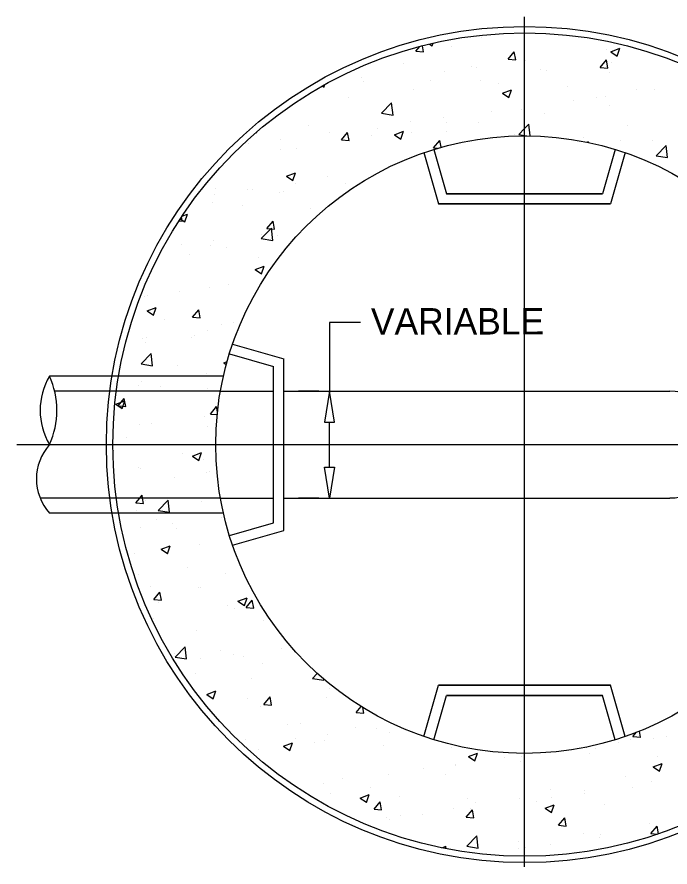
# Model space of a CAD drawing. Extents: x 6712067 to 6713867, y 1867712 to 1869162.
# Drawn here: x 6713210.3 to 6713358.3, y 1867926.4 to 1868119 of the extents above; entities that cross this region are included whole.
import ezdxf

# ---------------------------------------------------------------- set-up
doc = ezdxf.new("R2010")
doc.units = 0
for name, color, linetype in [('G-MARK', 7, 'Continuous'), ('G-TEXT', 7, 'Continuous'), ('Misc CnstDet(22)', 7, 'Continuous')]:
    doc.layers.add(name, color=color, linetype=linetype)

msp = doc.modelspace()

# ---------------------------------------------------------------- linework, layer by layer
at = {"layer": 'G-MARK'}
for p, q in [((6713288.14, 1868049.81), (6713281.14, 1868049.81)), ((6713281.14, 1868049.81), (6713281.14, 1868034.25)), ((6713281.14, 1868017.05), (6713281.14, 1868027.26))]:
    msp.add_line(p, q, dxfattribs=at)
at = {"layer": 'G-TEXT'}
for points in [[(6713279.98, 1868027.26), (6713282.31, 1868027.26), (6713281.14, 1868034.25)], [(6713279.98, 1868017.05), (6713282.31, 1868017.05), (6713281.14, 1868010.04)]]:
    msp.add_lwpolyline(points, close=True, dxfattribs=at)
at = {"layer": 'Misc CnstDet(22)'}
for p, q in [((6713325.33, 1867926.44), (6713325.33, 1868119.03)), ((6713325.89, 1868115.36), (6713325.89, 1868115.36)), ((6713303.83, 1868112.91), (6713304.41, 1868112.52)), ((6713304.4, 1868112.52), (6713304.6, 1868113.1)), ((6713315.65, 1868114.46), (6713315.65, 1868114.46)), ((6713300.68, 1868111.28), (6713301.58, 1868112.35)), ((6713300.68, 1868111.28), (6713302.43, 1868111.13)), ((6713302.43, 1868111.13), (6713302.18, 1868112.5)), ((6713308.89, 1868112.44), (6713308.89, 1868112.44)), ((6713321.59, 1868109.46), (6713322.99, 1868111.13)), ((6713323.34, 1868109.3), (6713322.99, 1868111.12)), ((6713344.01, 1868111.58), (6713344.01, 1868111.58)), ((6713344.85, 1868111.17), (6713346.89, 1868111.95)), ((6713344.85, 1868111.17), (6713346.3, 1868110.19)), ((6713346.3, 1868110.18), (6713346.89, 1868111.95)), ((6713321.59, 1868109.46), (6713323.34, 1868109.3)), ((6713325.6, 1868109.16), (6713325.6, 1868109.16)), ((6713342.5, 1868107.62), (6713343.9, 1868109.3)), ((6713344.24, 1868107.47), (6713343.9, 1868109.3)), ((6713297.81, 1868108.52), (6713297.81, 1868108.52)), ((6713313.38, 1868107.86), (6713313.38, 1868107.86)), ((6713314.56, 1868107.7), (6713314.56, 1868107.7)), ((6713328.94, 1868107.21), (6713328.94, 1868107.21)), ((6713342.5, 1868107.62), (6713344.24, 1868107.47)), ((6713344.98, 1868108.68), (6713344.98, 1868108.68)), ((6713288.4, 1868105.26), (6713288.4, 1868105.26)), ((6713307.26, 1868106.75), (6713307.26, 1868106.75)), ((6713330.26, 1868106.81), (6713330.26, 1868106.81)), ((6713344.5, 1868106.54), (6713344.5, 1868106.54)), ((6713279.51, 1868103.4), (6713279.91, 1868103.12)), ((6713279.91, 1868103.12), (6713280.12, 1868103.74)), ((6713288.85, 1868104.32), (6713288.85, 1868104.32)), ((6713303.97, 1868104.6), (6713303.97, 1868104.6)), ((6713315.29, 1868104.75), (6713315.29, 1868104.75)), ((6713319.53, 1868103.95), (6713319.53, 1868103.95)), ((6713335.09, 1868103.28), (6713335.09, 1868103.28)), ((6713300.16, 1868102.57), (6713300.16, 1868102.57)), ((6713320.35, 1868101.77), (6713322.4, 1868102.55)), ((6713320.35, 1868101.77), (6713321.81, 1868100.78)), ((6713321.81, 1868100.78), (6713322.4, 1868102.55)), ((6713350.65, 1868102.63), (6713350.65, 1868102.63)), ((6713354.67, 1868102.5), (6713354.67, 1868102.5)), ((6713285.43, 1868100.7), (6713285.43, 1868100.7)), ((6713292.94, 1868097.21), (6713295.21, 1868099.58)), ((6713295.53, 1868096.81), (6713295.21, 1868099.58)), ((6713336.34, 1868100.08), (6713336.34, 1868100.08)), ((6713341.68, 1868100.89), (6713341.68, 1868100.89)), ((6713343.64, 1868101.05), (6713343.64, 1868101.05)), ((6713317.93, 1868097.66), (6713317.93, 1868097.66)), ((6713324.68, 1868097.97), (6713324.68, 1868097.97)), ((6713344.63, 1868098.97), (6713344.63, 1868098.97)), ((6713292.94, 1868097.21), (6713295.53, 1868096.81)), ((6713306.89, 1868096.2), (6713306.89, 1868096.2)), ((6713329.9, 1868097.1), (6713329.9, 1868097.1)), ((6713276.46, 1868094.36), (6713276.46, 1868094.36)), ((6713292.02, 1868093.7), (6713292.02, 1868093.7)), ((6713299.59, 1868095.25), (6713299.59, 1868095.25)), ((6713307.68, 1868095.06), (6713307.68, 1868095.06)), ((6713314.94, 1868095.06), (6713314.94, 1868095.06)), ((6713324.05, 1868092.38), (6713325.33, 1868093.73)), ((6713325.33, 1868093.73), (6713326.32, 1868094.76)), ((6713326.63, 1868092.1), (6713326.32, 1868094.76)), ((6713348.66, 1868094.48), (6713348.66, 1868094.48)), ((6713264.52, 1868092.88), (6713264.65, 1868092.86)), ((6713264.65, 1868092.86), (6713264.64, 1868092.98)), ((6713281.19, 1868092.83), (6713281.19, 1868092.83)), ((6713283.83, 1868091.19), (6713285.23, 1868092.86)), ((6713285.56, 1868091.03), (6713285.23, 1868092.86)), ((6713290.68, 1868092.13), (6713290.68, 1868092.13)), ((6713295.86, 1868092.36), (6713297.91, 1868093.15)), ((6713295.86, 1868092.36), (6713297.32, 1868091.38)), ((6713297.31, 1868091.38), (6713297.91, 1868093.15)), ((6713299.8, 1868092.86), (6713299.8, 1868092.86)), ((6713307.58, 1868093.05), (6713307.58, 1868093.05)), ((6713323.14, 1868092.38), (6713323.14, 1868092.38)), ((6713324.05, 1868092.38), (6713325.33, 1868092.19)), ((6713325.33, 1868092.19), (6713325.89, 1868092.11)), ((6713338.7, 1868091.73), (6713338.7, 1868091.73)), ((6713262.85, 1868090.41), (6713262.85, 1868090.41)), ((6713270.15, 1868091.37), (6713270.15, 1868091.37)), ((6713283.83, 1868091.19), (6713285.56, 1868091.04)), ((6713285.08, 1868091.01), (6713285.08, 1868091.01)), ((6713304.72, 1868089.36), (6713306.13, 1868091.03)), ((6713306.41, 1868089.5), (6713306.13, 1868091.03)), ((6713339.43, 1868090.67), (6713339.79, 1868090.81)), ((6713339.73, 1868090.6), (6713339.79, 1868090.81)), ((6713347, 1868091.01), (6713347, 1868091.01)), ((6713354.27, 1868091.07), (6713354.27, 1868091.07)), ((6713355.16, 1868087.56), (6713357.43, 1868089.93)), ((6713357.75, 1868087.16), (6713357.43, 1868089.93)), ((6713270.11, 1868088.95), (6713270.11, 1868088.95)), ((6713273.68, 1868089.22), (6713273.68, 1868089.22)), ((6713302.54, 1868088.3), (6713305.87, 1868076.66)), ((6713302.54, 1868088.3), (6713305.87, 1868076.66)), ((6713304.72, 1868089.36), (6713305.64, 1868089.28)), ((6713304.77, 1868089.02), (6713307.63, 1868078.99)), ((6713304.77, 1868089.02), (6713307.63, 1868078.99)), ((6713345.89, 1868089.02), (6713343.03, 1868078.99)), ((6713345.89, 1868089.02), (6713343.03, 1868078.99)), ((6713348.11, 1868088.3), (6713344.79, 1868076.66)), ((6713348.11, 1868088.3), (6713344.79, 1868076.66)), ((6713355.16, 1868087.56), (6713357.75, 1868087.16)), ((6713271.37, 1868082.96), (6713273.42, 1868083.75)), ((6713271.37, 1868082.96), (6713272.82, 1868081.99)), ((6713272.82, 1868081.99), (6713273.42, 1868083.74)), ((6713280.67, 1868082.81), (6713280.67, 1868082.81)), ((6713291.92, 1868083.75), (6713291.92, 1868083.75)), ((6713255.22, 1868080.13), (6713255.22, 1868080.13)), ((6713273.51, 1868081.33), (6713273.51, 1868081.33)), ((6713284.72, 1868081.3), (6713284.72, 1868081.3)), ((6713255.17, 1868078.91), (6713255.17, 1868078.91)), ((6713262.47, 1868079.87), (6713262.47, 1868079.87)), ((6713263.66, 1868079.9), (6713263.66, 1868079.9)), ((6713269.76, 1868079.24), (6713269.76, 1868079.24)), ((6713270.78, 1868079.46), (6713270.78, 1868079.46)), ((6713307.63, 1868078.99), (6713343.03, 1868078.99)), ((6713343.03, 1868078.99), (6713307.63, 1868078.99)), ((6713254.62, 1868077.06), (6713254.62, 1868077.06)), ((6713261.37, 1868076.21), (6713261.37, 1868076.21)), ((6713305.87, 1868076.66), (6713344.79, 1868076.66)), ((6713344.79, 1868076.66), (6713305.87, 1868076.66)), ((6713247.71, 1868073.88), (6713248.93, 1868074.34)), ((6713248.33, 1868072.59), (6713248.93, 1868074.34)), ((6713276.93, 1868075.55), (6713276.93, 1868075.55)), ((6713247.02, 1868072.84), (6713247.79, 1868072.77)), ((6713247.31, 1868073.27), (6713248.33, 1868072.59)), ((6713247.79, 1868072.77), (6713247.61, 1868073.73)), ((6713266.96, 1868071.09), (6713268.37, 1868072.77)), ((6713268.7, 1868070.93), (6713268.36, 1868072.76)), ((6713265.69, 1868068.82), (6713267.97, 1868071.19)), ((6713266.96, 1868071.09), (6713268.7, 1868070.93)), ((6713268.29, 1868068.41), (6713267.97, 1868071.19)), ((6713254.8, 1868068.37), (6713254.8, 1868068.37)), ((6713265.69, 1868068.82), (6713268.29, 1868068.42)), ((6713265.84, 1868069.83), (6713265.84, 1868069.83)), ((6713269.4, 1868069.55), (6713269.4, 1868069.55)), ((6713247.5, 1868067.42), (6713247.5, 1868067.42)), ((6713254.26, 1868067.35), (6713254.26, 1868067.35)), ((6713257.8, 1868066.78), (6713257.8, 1868066.78)), ((6713249.42, 1868065.31), (6713249.42, 1868065.31)), ((6713264.98, 1868064.64), (6713264.98, 1868064.64)), ((6713264.28, 1868061.82), (6713266.32, 1868062.61)), ((6713265.73, 1868060.85), (6713266.32, 1868062.6)), ((6713264.28, 1868061.82), (6713265.73, 1868060.85)), ((6713247.14, 1868056.88), (6713247.14, 1868056.88)), ((6713253.91, 1868057.66), (6713253.91, 1868057.66)), ((6713258.18, 1868058.33), (6713258.18, 1868058.33)), ((6713239.18, 1868055.79), (6713239.18, 1868055.79)), ((6713239.84, 1868055.92), (6713239.84, 1868055.92)), ((6713239.79, 1868052.42), (6713241.83, 1868053.2)), ((6713241.24, 1868051.45), (6713241.83, 1868053.2)), ((6713239.79, 1868052.42), (6713241.24, 1868051.45)), ((6713250.1, 1868051), (6713251.5, 1868052.68)), ((6713251.83, 1868050.84), (6713251.5, 1868052.66)), ((6713243.75, 1868050.41), (6713243.75, 1868050.41)), ((6713250.1, 1868051), (6713251.84, 1868050.84)), ((6713256.59, 1868049.38), (6713256.59, 1868049.38)), ((6713259.3, 1868049.75), (6713259.3, 1868049.75)), ((6713253.55, 1868047.95), (6713253.55, 1868047.95)), ((6713238.83, 1868046.08), (6713238.83, 1868046.08)), ((6713239.47, 1868045.39), (6713239.47, 1868045.39)), ((6713239.6, 1868046.47), (6713239.6, 1868046.47)), ((6713249.89, 1868046.49), (6713249.89, 1868046.49)), ((6713250.51, 1868046.83), (6713250.51, 1868046.83)), ((6713259.19, 1868044.93), (6713270.82, 1868041.6)), ((6713238.45, 1868040.42), (6713240.72, 1868042.79)), ((6713241.04, 1868040.02), (6713240.72, 1868042.78)), ((6713258.46, 1868042.71), (6713268.49, 1868039.85)), ((6713270.82, 1868002.69), (6713270.82, 1868041.6)), ((6713238.45, 1868040.42), (6713241.04, 1868040.02)), ((6713246.59, 1868040.06), (6713246.59, 1868040.06)), ((6713257.19, 1868040.68), (6713257.96, 1868040.98)), ((6713257.19, 1868040.68), (6713257.76, 1868040.3)), ((6713268.49, 1868004.45), (6713268.49, 1868039.85)), ((6713231.87, 1868037.68), (6713217.69, 1868037.68)), ((6713257.12, 1868037.68), (6713231.87, 1868037.68)), ((6713253.2, 1868038.25), (6713253.2, 1868038.25)), ((6713238.47, 1868036.38), (6713238.47, 1868036.38)), ((6713256.42, 1868034.25), (6713218.86, 1868034.25)), ((6713237.94, 1868035.6), (6713237.94, 1868035.6)), ((6713242.84, 1868035.34), (6713242.84, 1868035.34)), ((6713253.51, 1868034.93), (6713253.51, 1868034.93)), ((6713256.42, 1868034.25), (6713268.49, 1868034.25)), ((6713270.82, 1868034.25), (6713358.25, 1868034.25)), ((6713278.69, 1868034.25), (6713274.15, 1868034.25)), ((6713281.14, 1868034.25), (6713281.14, 1868034.25)), ((6713281.14, 1868034.25), (6713281.14, 1868034.25)), ((6713232.7, 1868031.28), (6713234.74, 1868032.08)), ((6713233.23, 1868030.89), (6713234.64, 1868032.57)), ((6713234.15, 1868030.31), (6713234.74, 1868032.06)), ((6713234.97, 1868030.74), (6713234.64, 1868032.57)), ((6713232.7, 1868031.28), (6713234.15, 1868030.31)), ((6713233.23, 1868030.89), (6713234.97, 1868030.74)), ((6713254.14, 1868029.07), (6713255.55, 1868030.74)), ((6713255.77, 1868029.55), (6713255.54, 1868030.74)), ((6713252.84, 1868028.54), (6713252.84, 1868028.54)), ((6713254.14, 1868029.07), (6713255.7, 1868028.93)), ((6713238.12, 1868026.67), (6713238.12, 1868026.67)), ((6713240.71, 1868026.95), (6713240.71, 1868026.95)), ((6713253.57, 1868026.27), (6713253.57, 1868026.27)), ((6713210.33, 1868022.15), (6713440.32, 1868022.15)), ((6713235.17, 1868023.85), (6713235.17, 1868023.85)), ((6713232.28, 1868020.7), (6713232.28, 1868020.7)), ((6713250.1, 1868019.56), (6713252.14, 1868020.34)), ((6713251.54, 1868018.57), (6713252.14, 1868020.34)), ((6713247.83, 1868020.04), (6713247.83, 1868020.04)), ((6713250.1, 1868019.56), (6713251.54, 1868018.57)), ((6713252.48, 1868018.83), (6713252.48, 1868018.83)), ((6713237.76, 1868016.97), (6713237.76, 1868016.97)), ((6713238.42, 1868016.78), (6713238.42, 1868016.78)), ((6713245.91, 1868014.77), (6713245.91, 1868014.77)), ((6713253.21, 1868015.73), (6713253.21, 1868015.73)), ((6713253.98, 1868016.12), (6713253.98, 1868016.12)), ((6713238.17, 1868010.04), (6713238.68, 1868010.65)), ((6713238.79, 1868010.04), (6713238.68, 1868010.65)), ((6713256.42, 1868010.04), (6713215.58, 1868010.04)), ((6713237.28, 1868008.97), (6713238.17, 1868010.04)), ((6713237.28, 1868008.97), (6713239.02, 1868008.83)), ((6713239.01, 1868008.81), (6713238.79, 1868010.04)), ((6713239.51, 1868009.56), (6713239.51, 1868009.56)), ((6713242.32, 1868007.21), (6713244.59, 1868009.57)), ((6713244.91, 1868006.81), (6713244.59, 1868009.57)), ((6713252.13, 1868009.14), (6713252.13, 1868009.14)), ((6713256.42, 1868010.04), (6713268.49, 1868010.04)), ((6713270.82, 1868010.04), (6713358.25, 1868010.04)), ((6713278.69, 1868010.04), (6713274.15, 1868010.04)), ((6713281.14, 1868010.04), (6713281.14, 1868010.04)), ((6713237.41, 1868007.26), (6713237.41, 1868007.26)), ((6713242.32, 1868007.21), (6713244.91, 1868006.81)), ((6713231.87, 1868006.62), (6713217.69, 1868006.62)), ((6713257.12, 1868006.62), (6713231.87, 1868006.62)), ((6713242.03, 1868005.22), (6713242.03, 1868005.22)), ((6713256.58, 1868005.69), (6713256.58, 1868005.69)), ((6713238.24, 1868003.27), (6713238.24, 1868003.27)), ((6713245.54, 1868004.24), (6713245.54, 1868004.24)), ((6713246.49, 1868003.16), (6713246.49, 1868003.16)), ((6713257.59, 1868004.57), (6713257.59, 1868004.57)), ((6713258.46, 1868001.58), (6713268.49, 1868004.45)), ((6713259.19, 1867999.37), (6713270.82, 1868002.69)), ((6713243.01, 1867998.42), (6713245.05, 1867999.2)), ((6713244.45, 1867997.43), (6713245.05, 1867999.2)), ((6713251.78, 1867999.43), (6713251.78, 1867999.43)), ((6713237.06, 1867997.57), (6713237.06, 1867997.57)), ((6713243.01, 1867998.42), (6713244.45, 1867997.44)), ((6713248.92, 1867994.19), (6713248.92, 1867994.19)), ((6713237.88, 1867992.74), (6713237.88, 1867992.74)), ((6713257.63, 1867992.95), (6713257.63, 1867992.95)), ((6713240.63, 1867990.04), (6713240.63, 1867990.04)), ((6713251.43, 1867989.73), (6713251.43, 1867989.73)), ((6713251.91, 1867989.67), (6713251.91, 1867989.67)), ((6713241.32, 1867987.04), (6713242.73, 1867988.72)), ((6713243.06, 1867986.9), (6713242.72, 1867988.72)), ((6713241.32, 1867987.04), (6713243.06, 1867986.9)), ((6713242.5, 1867986.41), (6713242.5, 1867986.41)), ((6713258.06, 1867985.76), (6713258.06, 1867985.76)), ((6713260.4, 1867986.68), (6713262.45, 1867987.46)), ((6713260.4, 1867986.68), (6713261.85, 1867985.7)), ((6713261.85, 1867985.7), (6713262.45, 1867987.46)), ((6713262.23, 1867985.22), (6713263.63, 1867986.9)), ((6713263.97, 1867985.06), (6713263.63, 1867986.9)), ((6713259.66, 1867985.12), (6713259.66, 1867985.12)), ((6713262.23, 1867985.22), (6713263.97, 1867985.07)), ((6713241.25, 1867982.69), (6713241.25, 1867982.69)), ((6713266.21, 1867982.21), (6713266.21, 1867982.21)), ((6713251.07, 1867980.02), (6713251.07, 1867980.02)), ((6713246.18, 1867973.98), (6713248.45, 1867976.35)), ((6713248.77, 1867973.58), (6713248.45, 1867976.35)), ((6713270.32, 1867976.04), (6713270.32, 1867976.04)), ((6713246.12, 1867974.86), (6713246.12, 1867974.86)), ((6713256.42, 1867975.57), (6713256.42, 1867975.57)), ((6713259.28, 1867974.58), (6713259.28, 1867974.58)), ((6713261.68, 1867974.2), (6713261.68, 1867974.2)), ((6713246.18, 1867973.98), (6713248.77, 1867973.58)), ((6713251.98, 1867973.62), (6713251.98, 1867973.62)), ((6713265.85, 1867972.5), (6713265.85, 1867972.5)), ((6713250.72, 1867970.32), (6713250.72, 1867970.32)), ((6713277.28, 1867969.16), (6713278.37, 1867970.29)), ((6713263.41, 1867969.16), (6713263.41, 1867969.16)), ((6713277.28, 1867969.16), (6713279.88, 1867968.76)), ((6713279.88, 1867968.75), (6713279.85, 1867968.99)), ((6713253.31, 1867965.54), (6713255.35, 1867966.32)), ((6713254.76, 1867964.56), (6713255.35, 1867966.32)), ((6713281.06, 1867966.96), (6713281.06, 1867966.96)), ((6713302.54, 1867956), (6713305.87, 1867967.64)), ((6713302.54, 1867956), (6713305.87, 1867967.64)), ((6713305.87, 1867967.64), (6713344.79, 1867967.64)), ((6713344.79, 1867967.64), (6713305.87, 1867967.64)), ((6713348.11, 1867956), (6713344.79, 1867967.64)), ((6713348.11, 1867956), (6713344.79, 1867967.64)), ((6713253.31, 1867965.54), (6713254.76, 1867964.56)), ((6713262.65, 1867964.54), (6713262.65, 1867964.54)), ((6713266.27, 1867963.29), (6713267.68, 1867964.96)), ((6713268.01, 1867963.14), (6713267.68, 1867964.96)), ((6713280.46, 1867964.85), (6713280.46, 1867964.85)), ((6713304.77, 1867955.28), (6713307.63, 1867965.31)), ((6713304.77, 1867955.28), (6713307.63, 1867965.31)), ((6713307.63, 1867965.31), (6713343.03, 1867965.31)), ((6713343.03, 1867965.31), (6713307.63, 1867965.31)), ((6713345.89, 1867955.28), (6713343.03, 1867965.31)), ((6713345.89, 1867955.28), (6713343.03, 1867965.31)), ((6713265.5, 1867962.81), (6713265.5, 1867962.81)), ((6713266.27, 1867963.29), (6713268.01, 1867963.14)), ((6713287.18, 1867961.46), (6713288.3, 1867962.8)), ((6713288.92, 1867961.3), (6713288.69, 1867962.55)), ((6713287.18, 1867961.46), (6713288.92, 1867961.32)), ((6713271.56, 1867958.64), (6713271.56, 1867958.64)), ((6713274.54, 1867958.96), (6713274.54, 1867958.96)), ((6713287.12, 1867957.99), (6713287.12, 1867957.99)), ((6713291.73, 1867957.88), (6713291.73, 1867957.88)), ((6713294.83, 1867957.01), (6713294.83, 1867957.01)), ((6713349.9, 1867955.98), (6713350.73, 1867956.97)), ((6713351.64, 1867955.82), (6713351.38, 1867957.22)), ((6713262.15, 1867955.39), (6713262.15, 1867955.39)), ((6713273.39, 1867955.46), (6713273.39, 1867955.46)), ((6713280.12, 1867955.15), (6713280.12, 1867955.15)), ((6713280.69, 1867956.43), (6713280.69, 1867956.43)), ((6713349.36, 1867955.36), (6713349.36, 1867955.36)), ((6713349.9, 1867955.98), (6713351.65, 1867955.82)), ((6713354.45, 1867955.6), (6713354.45, 1867955.6)), ((6713357.56, 1867956.06), (6713357.56, 1867956.06)), ((6713265.14, 1867953.1), (6713265.14, 1867953.1)), ((6713270.71, 1867953.81), (6713272.75, 1867954.59)), ((6713270.71, 1867953.81), (6713272.17, 1867952.82)), ((6713272.15, 1867952.82), (6713272.75, 1867954.59)), ((6713277.71, 1867954.73), (6713277.71, 1867954.73)), ((6713293.27, 1867954.07), (6713293.27, 1867954.07)), ((6713308.83, 1867953.42), (6713308.83, 1867953.42)), ((6713339.31, 1867953.42), (6713339.31, 1867953.42)), ((6713341.33, 1867953.25), (6713341.33, 1867953.25)), ((6713346.52, 1867954.6), (6713346.52, 1867954.6)), ((6713312.61, 1867951.47), (6713314.64, 1867952.25)), ((6713312.61, 1867951.47), (6713314.05, 1867950.49)), ((6713314.05, 1867950.49), (6713314.64, 1867952.25)), ((6713320.81, 1867951.22), (6713320.81, 1867951.22)), ((6713324.59, 1867951.55), (6713324.59, 1867951.55)), ((6713339.94, 1867952.1), (6713339.94, 1867952.1)), ((6713355.5, 1867951.45), (6713355.5, 1867951.45)), ((6713309.62, 1867949.49), (6713309.62, 1867949.49)), ((6713309.77, 1867949.77), (6713309.77, 1867949.77)), ((6713324.34, 1867950.32), (6713324.34, 1867950.32)), ((6713354.49, 1867949.14), (6713356.54, 1867949.92)), ((6713354.49, 1867949.14), (6713355.94, 1867948.15)), ((6713355.94, 1867948.15), (6713356.54, 1867949.92)), ((6713294.49, 1867947.31), (6713294.49, 1867947.31)), ((6713302.47, 1867948.81), (6713302.47, 1867948.81)), ((6713307.34, 1867947.41), (6713307.34, 1867947.41)), ((6713279.76, 1867945.44), (6713279.76, 1867945.44)), ((6713284.07, 1867946.38), (6713284.07, 1867946.38)), ((6713348.32, 1867946.84), (6713348.32, 1867946.84)), ((6713354.09, 1867945.9), (6713354.09, 1867945.9)), ((6713273.03, 1867944.93), (6713273.03, 1867944.93)), ((6713290.33, 1867944.49), (6713290.33, 1867944.49)), ((6713331.32, 1867943.93), (6713331.32, 1867943.93)), ((6713338.96, 1867943.71), (6713338.96, 1867943.71)), ((6713349.88, 1867944.56), (6713349.88, 1867944.56)), ((6713281.32, 1867943.17), (6713281.32, 1867943.17)), ((6713288.11, 1867942.07), (6713290.15, 1867942.85)), ((6713288.11, 1867942.07), (6713289.56, 1867941.09)), ((6713289.56, 1867941.08), (6713290.15, 1867942.85)), ((6713296.89, 1867942.52), (6713296.89, 1867942.52)), ((6713312.45, 1867941.85), (6713312.45, 1867941.85)), ((6713324.23, 1867941.85), (6713324.23, 1867941.85)), ((6713331.55, 1867942.15), (6713331.55, 1867942.15)), ((6713338.84, 1867943.11), (6713338.84, 1867943.11)), ((6713291.23, 1867939.53), (6713292.63, 1867941.21)), ((6713291.23, 1867939.53), (6713292.96, 1867939.38)), ((6713292.96, 1867939.38), (6713292.63, 1867941.21)), ((6713309.27, 1867939.8), (6713309.27, 1867939.8)), ((6713312.14, 1867937.71), (6713313.54, 1867939.38)), ((6713313.14, 1867939.73), (6713313.14, 1867939.73)), ((6713313.87, 1867937.55), (6713313.54, 1867939.38)), ((6713314.32, 1867941), (6713314.32, 1867941)), ((6713328.01, 1867941.2), (6713328.01, 1867941.2)), ((6713330, 1867939.73), (6713332.05, 1867940.52)), ((6713330, 1867939.73), (6713331.45, 1867938.75)), ((6713331.45, 1867938.75), (6713332.04, 1867940.52)), ((6713343.56, 1867940.54), (6713343.56, 1867940.54)), ((6713294.13, 1867937.61), (6713294.13, 1867937.61)), ((6713297.32, 1867938.09), (6713297.32, 1867938.09)), ((6713302.11, 1867938.27), (6713302.11, 1867938.27)), ((6713312.14, 1867937.71), (6713313.87, 1867937.56)), ((6713333.03, 1867935.88), (6713334.45, 1867937.55)), ((6713334.78, 1867935.72), (6713334.45, 1867937.55)), ((6713294.81, 1867937.31), (6713294.81, 1867937.31)), ((6713333.03, 1867935.88), (6713334.78, 1867935.72)), ((6713353.74, 1867936.19), (6713353.74, 1867936.19)), ((6713353.94, 1867934.05), (6713355.36, 1867935.72)), ((6713355.68, 1867933.94), (6713355.36, 1867935.72)), ((6713338.6, 1867934.01), (6713338.6, 1867934.01)), ((6713342.46, 1867933.73), (6713342.46, 1867933.73)), ((6713353.94, 1867934.05), (6713355.56, 1867933.91)), ((6713312.26, 1867931.12), (6713314.54, 1867933.49)), ((6713314.86, 1867930.71), (6713314.54, 1867933.49)), ((6713323.88, 1867932.14), (6713323.88, 1867932.14)), ((6713342.22, 1867933.06), (6713342.22, 1867933.06)), ((6713306.63, 1867930.77), (6713307.55, 1867931.12)), ((6713307.39, 1867930.62), (6713307.55, 1867931.11)), ((6713312.26, 1867931.12), (6713314.86, 1867930.71)), ((6713323.88, 1867930.65), (6713323.88, 1867930.65)), ((6713325.45, 1867930.8), (6713325.45, 1867930.8)), ((6713331.18, 1867931.62), (6713331.18, 1867931.62))]:
    msp.add_line(p, q, dxfattribs=at)
for radius in [94.73, 93.28, 69.96]:
    msp.add_circle((6713325.33, 1868022.15), radius, dxfattribs=at)
for centre, radius, start, end in [((6713230.89, 1868029.91), 15.32, 149.5444, 210.4556), ((6713200.55, 1868029.91), 18.82, 335.6342, 24.3658), ((6713358.24, 1868022.15), 12.1, 270, 90), ((6713226.45, 1868014.38), 11.71, 138.4565, 221.5435)]:
    msp.add_arc(centre, radius, start, end, dxfattribs=at)

# ---------------------------------------------------------------- texts
msp.add_text('VARIABLE', height=6, rotation=0.1, dxfattribs=at).set_placement((6713290.53, 1868047.04))

doc.saveas('drawing.dxf')
